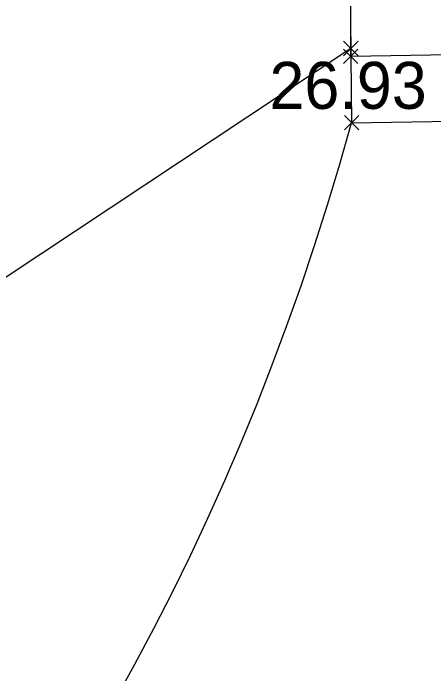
# Model space of a CAD drawing. Extents: x 37864 to 38032, y 453991 to 454052.
# Drawn here: x 37880.939 to 37883.488, y 454000.734 to 454004.739 of the extents above; entities that cross this region are included whole.
import ezdxf

# ---------------------------------------------------------------- set-up
doc = ezdxf.new("R2010")
doc.units = 0
for name, color, linetype in [('DH_CALCUL SURFACE-TEXTE', 7, 'Continuous'), ('GO_POTEAU', 7, 'Continuous'), ('PS_Bolt', 7, 'Continuous'), ('PS_Dim', 7, 'Continuous'), ('PS_Object', 7, 'Continuous'), ('SO_SANITAIRE DETAILLE', 7, 'Continuous')]:
    doc.layers.add(name, color=color, linetype=linetype)

# ---------------------------------------------------------------- blocks, each defined once
blk = doc.blocks.new('POINT_DISPLAY')
for p, q in [((-0.04375, -0.04375), (0.04375, 0.04375)), ((-0.04375, 0.04375), (0.04375, -0.04375))]:
    blk.add_line(p, q)
blk = doc.blocks.new('POINTCOT')
blk.add_blockref('POINT_DISPLAY', (0, 0))

msp = doc.modelspace()

# ---------------------------------------------------------------- linework, layer by layer
at = {"layer": 'PS_Bolt'}
msp.add_lwpolyline([(37883.5913, 454004.4858), (37882.9848, 454004.477), (37882.99, 454004.0752), (37883.5971, 454004.084), (37883.5913, 454004.4858)], dxfattribs=at)
at = {"layer": 'PS_Dim'}
msp.add_line((37882.9848, 454004.477), (37882.9848, 454030.3981), dxfattribs=at)
msp.add_lwpolyline([(37882.9853, 454004.5251), (37878.1935, 454001.3462), (37873.0842, 454001.1016), (37864.3543, 454000.9867)], dxfattribs=at)
at = {"layer": 'PS_Object'}
msp.add_lwpolyline([(37895.242, 454005.2637), (37889.9429, 454005.1784), (37889.9169, 454004.7056), (37883.5913, 454004.4858), (37882.9848, 454004.477), (37882.9848, 454030.3981)], dxfattribs=at)
at = {"layer": 'SO_SANITAIRE DETAILLE'}
msp.add_line((37882.9848, 454004.477), (37882.9848, 454030.2847), dxfattribs=at)
msp.add_lwpolyline([(37877.7672, 454040.9193), (37880.278, 454037.4083), (37879.922, 454031.2706), (37881.6011, 454024.1531), (37881.6011, 454024.1531), (37881.6011, 454024.1531), (37881.675, 454023.8212), (37881.7814, 454022.2666), (37881.9007, 454020.7687), (37881.9266, 454020.3896), (37882.0081, 454019.1046), (37882.1138, 454018.1338), (37882.5612, 454015.4301), (37882.6563, 454013.5927), (37882.5766, 454012.1196), (37882.5924, 454010.9245), (37882.7852, 454009.3668), (37882.9596, 454007.5875), (37882.9848, 454004.477)], dxfattribs=at)
msp.add_ellipse((37874.8135, 454006.2064), major_axis=(3.217, 11.0946), ratio=0.731344, start_param=3.344921, end_param=4.732315, dxfattribs=at)

# ---------------------------------------------------------------- block references
at = {"layer": 'DH_CALCUL SURFACE-TEXTE', "rotation": 2.2526485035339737e-05}
for p in [(37882.9853, 454004.5251), (37882.9848, 454004.477), (37882.99, 454004.0752)]:
    msp.add_blockref('POINTCOT', p, dxfattribs=at)

# ---------------------------------------------------------------- texts
at = {"layer": 'GO_POTEAU'}
msp.add_text('26.93', height=0.285, rotation=0, dxfattribs=at).set_placement((37882.492, 454004.159))

doc.saveas('drawing.dxf')
